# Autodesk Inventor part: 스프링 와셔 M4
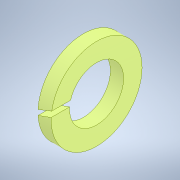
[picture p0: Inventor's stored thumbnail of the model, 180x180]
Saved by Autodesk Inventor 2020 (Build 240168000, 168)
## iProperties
Created: 2024-05
Part Number: 스프링 와셔 M4
Material: 강철, 연강
Description: 스프링 잠금 와셔
Document SubType Name: Modeling
Designer: oem
Density: 7.85 g/cm^3
Appearance: 기본값
Author: jhkim
Sending System: Autodesk Inventor 2025
Preprocessor: ST-DEVELOPER v20
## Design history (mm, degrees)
feature "Solid1"
node "솔리드1"
